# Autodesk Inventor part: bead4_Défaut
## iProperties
Shininess: 64.0
Length Units: 11269
Angle Units: 11279
Time Units: 11290
Mass Units: 11283
Length Display Precision: 3
Angle Display Precision: 2
Compacted: True
Part Number: bead4_Défaut
Document SubType Name: Modeling
Created: 2006-01
Material: Par défaut
Designer: Fricot
Density: 0.0
Volumn: 0.0
Area: 0.0
PropertySet Name: Model Information
Control State: 0
Master: False
Checked Out: False
Author: Fricot
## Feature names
1. Base1
